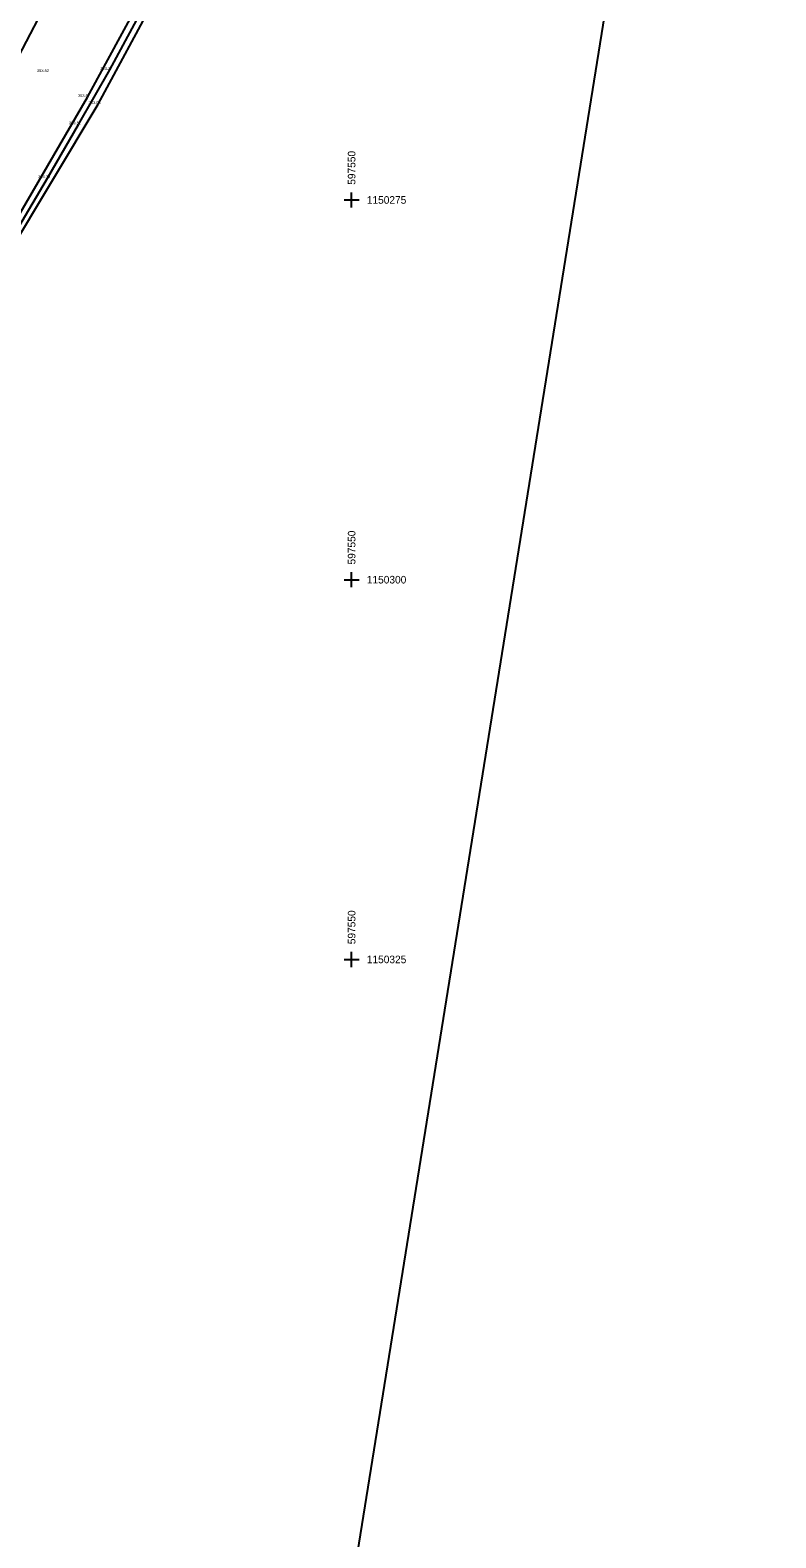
# Model space of a CAD drawing. Extents: x -600096 to -597522, y -1151695 to -1149849.
# Drawn here: x -597571.2 to -597522.1, y -1150363.1 to -1150263.8 of the extents above; entities that cross this region are included whole.
import ezdxf

# ---------------------------------------------------------------- set-up
doc = ezdxf.new("R2010")
doc.units = 0
for name, color, linetype in [('MPPV_komunikace', 7, 'Continuous'), ('MPPV_svah', 7, 'Continuous'), ('Ram03', 7, 'Continuous'), ('Svodidla', 7, 'Continuous'), ('Vrstva 12', 7, 'Continuous'), ('Vrstva 5', 7, 'Continuous')]:
    doc.layers.add(name, color=color, linetype=linetype)

msp = doc.modelspace()

# ---------------------------------------------------------------- linework, layer by layer
at = {"layer": 'MPPV_komunikace'}
for p, q in [((-597568.44, -1150258.85), (-597571.96, -1150265.57)), ((-597567.4, -1150268.23), (-597563.41, -1150260.92)), ((-597573.28, -1150278.33), (-597567.4, -1150268.23))]:
    msp.add_line(p, q, dxfattribs=at)
at = {"layer": 'MPPV_svah'}
for p, q in [((-597566.7, -1150268.69), (-597562.7, -1150261.3)), ((-597572.66, -1150278.66), (-597566.7, -1150268.69))]:
    msp.add_line(p, q, dxfattribs=at)
at = {"layer": 'Ram03'}
msp.add_line((-597613.724, -1150762.873), (-597522.061, -1150192.694), dxfattribs=at)
at = {"layer": 'Svodidla'}
for p, q in [((-597565.93, -1150266.44), (-597564.02, -1150262.91)), ((-597567.99, -1150270.03), (-597565.93, -1150266.44)), ((-597570.02, -1150273.56), (-597567.99, -1150270.03)), ((-597571.98, -1150276.89), (-597570.02, -1150273.56))]:
    msp.add_line(p, q, dxfattribs=at)
at = {"layer": 'Vrstva 5'}
for points in [[(-597550, -1150275.5), (-597550, -1150275), (-597550, -1150274.5)], [(-597550.5, -1150275), (-597550, -1150275), (-597549.5, -1150275)], [(-597550.5, -1150300), (-597550, -1150300), (-597549.5, -1150300)], [(-597550, -1150300.5), (-597550, -1150300), (-597550, -1150299.5)], [(-597550.5, -1150325), (-597550, -1150325), (-597549.5, -1150325)], [(-597550, -1150325.5), (-597550, -1150325), (-597550, -1150324.5)]]:
    msp.add_lwpolyline(points, dxfattribs=at)

# ---------------------------------------------------------------- texts
at = {"layer": 'Vrstva 12'}
for s, p in [('353.52 ', (-597570.725, -1150266.58)), ('353.27 ', (-597566.555, -1150266.44)), ('353.57 ', (-597568.025, -1150268.23)), ('353.05 ', (-597567.325, -1150268.69)), ('353.51 ', (-597568.615, -1150270.03)), ('353.70 ', (-597570.645, -1150273.56))]:
    msp.add_text(s, height=0.1875, dxfattribs=at).set_placement(p)
at = {"layer": 'Vrstva 5'}
for p in [(-597549.75, -1150274), (-597549.75, -1150299), (-597549.75, -1150324)]:
    msp.add_text('597550', height=0.5, rotation=90, dxfattribs=at).set_placement(p)
for s, p in [('1150275', (-597549, -1150275.25)), ('1150300', (-597549, -1150300.25)), ('1150325', (-597549, -1150325.25))]:
    msp.add_text(s, height=0.5, dxfattribs=at).set_placement(p)

doc.saveas('drawing.dxf')
